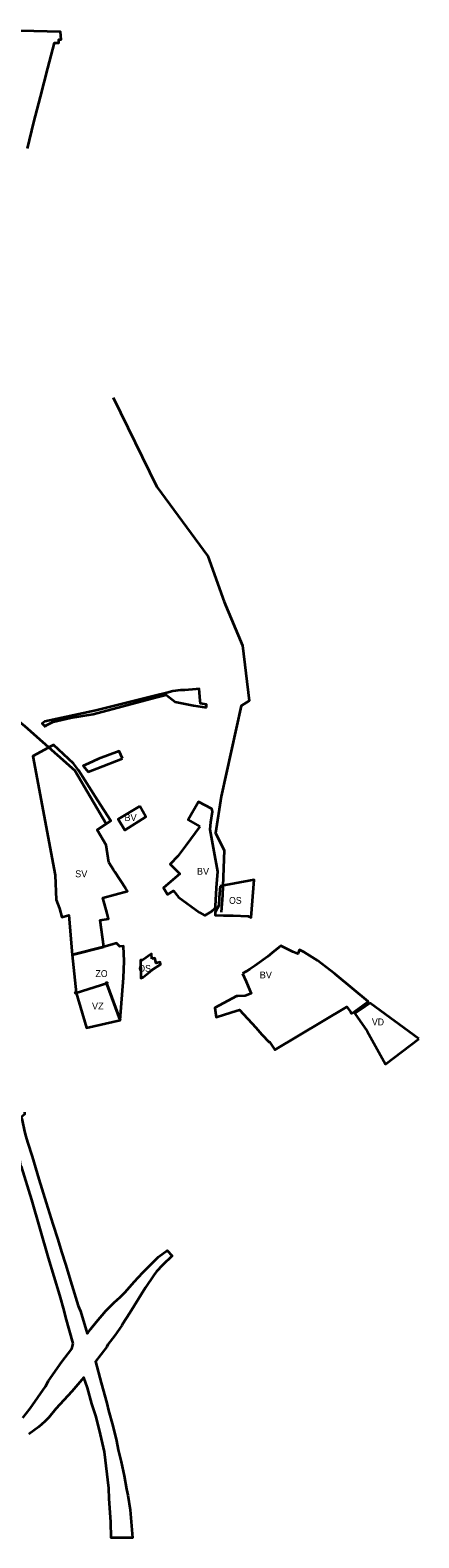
# Model space of a CAD drawing. Extents: x -650276 to -642489, y -1074311 to -1066658.
# Drawn here: x -645218 to -644537, y -1074038 to -1071399 of the extents above; entities that cross this region are included whole.
import ezdxf

# ---------------------------------------------------------------- set-up
doc = ezdxf.new("R2010")
doc.units = 0
doc.header["$LTSCALE"] = 4.8
doc.header["$PDMODE"] = 32
doc.header["$PDSIZE"] = 2.4
for name, color, linetype, lineweight in [('15', 7, 'Continuous', 35), ('18', 7, 'Continuous', 35), ('24', 7, 'Continuous', 35), ('3', 7, 'Continuous', 35), ('35', 7, 'Continuous', 35), ('36', 7, 'Continuous', 35), ('42', 7, 'Continuous', 35), ('54', 7, 'Continuous', 35), ('9', 7, 'Continuous', 35)]:
    doc.layers.add(name, color=color, linetype=linetype, lineweight=lineweight)
doc.layers.add('62', color=7, linetype='Continuous')

msp = doc.modelspace()

# ---------------------------------------------------------------- linework, layer by layer
at = {"layer": '15'}
for points in [[(-644926.81, -1072552.51), (-644946.57, -1072554.22), (-644954.57, -1072554.43), (-644967.97, -1072556.17), (-644978.56, -1072558.74), (-644999.72, -1072564.24), (-645102.73, -1072589.74), (-645192.06, -1072609.19), (-645197.044, -1072612.821), (-645190.71, -1072618.6)], [(-645147.13, -1072602.79), (-645107.58, -1072596.47), (-644997.92, -1072567.23), (-644979.55, -1072562.44), (-644963.97, -1072574.57)], [(-644919.75, -1072572.43), (-644921.84, -1072552.03), (-644926.81, -1072552.51)], [(-644963.97, -1072574.57), (-644931.48, -1072581.26), (-644909.02, -1072584.28)], [(-644909.02, -1072584.28), (-644908.59, -1072579.51), (-644919.23, -1072577.46), (-644919.75, -1072572.43)], [(-645190.71, -1072618.6), (-645190.59, -1072616.28), (-645179.6, -1072610.94), (-645177.56, -1072609.89), (-645147.13, -1072602.79)], [(-645056.08, -1072674.07), (-645062.131, -1072660.856), (-645098.016, -1072674.425), (-645115.56, -1072682.406), (-645124.933, -1072686.721), (-645116.11, -1072697.15)], [(-645116.11, -1072697.15), (-645100.9, -1072691.31), (-645056.08, -1072674.07)]]:
    msp.add_lwpolyline(points, dxfattribs=at)
at = {"layer": '18'}
msp.add_lwpolyline([(-645144.37, -1073017.64), (-645088.62, -1073003.45), (-645095.04, -1072957.07), (-645080.61, -1072954.43), (-645083.13, -1072944.94), (-645090.34, -1072917.86), (-645047.42, -1072906.05), (-645050.6, -1072901.03), (-645069.55, -1072872.12), (-645071.87, -1072868.45), (-645079.81, -1072855.89), (-645084.47, -1072825.67), (-645100.27, -1072798.46), (-645076.66, -1072783.06), (-645099.58, -1072746.945), (-645121.96, -1072711.68), (-645133.26, -1072694.17), (-645142.1, -1072682.57), (-645176.757, -1072649.968), (-645180.05, -1072651.77), (-645213.34, -1072669.98), (-645174.13, -1072877.93), (-645172.28, -1072921.42), (-645166.48, -1072936.5), (-645162.379, -1072951.55), (-645149.84, -1072948.13)], close=True, dxfattribs=at)
at = {"layer": '24'}
for points in [[(-645222.48, -1071606.08), (-645211.27, -1071560.01), (-645199.61, -1071515.68), (-645186.67, -1071465.55), (-645175.06, -1071420.93), (-645167.58, -1071421.19), (-645167.37, -1071415.2), (-645163.56, -1071415.3), (-645164.76, -1071401.79), (-645281.92, -1071398.82)], [(-645142.207, -1073697.878), (-645155.4, -1073652.618), (-645158.271, -1073639.962), (-645165.879, -1073613.368), (-645185.838, -1073547.75), (-645215.066, -1073446.251), (-645215.066, -1073446.251), (-645232.869, -1073388.079), (-645234.15, -1073388.3), (-645236.73, -1073372.92), (-645242.255, -1073352.652), (-645245.55, -1073343.196), (-645247.997, -1073332.992), (-645254.252, -1073315.648), (-645259.671, -1073298.157), (-645270.862, -1073292.263), (-645270.674, -1073289.436), (-645270.979, -1073285.096), (-645270.826, -1073282.937), (-645268.281, -1073278.357), (-645267.011, -1073277.282)], [(-645227.744, -1073292.736), (-645227.709, -1073297.105), (-645233.538, -1073301.748), (-645231.976, -1073307.175), (-645227.811, -1073326.92), (-645225.208, -1073335.374), (-645222.766, -1073345.378), (-645214.368, -1073370.824), (-645202.792, -1073410.042), (-645189.911, -1073451.528), (-645178.332, -1073489.109), (-645169.356, -1073515.725), (-645162.838, -1073537.623), (-645156.149, -1073559.097), (-645144.741, -1073595.63), (-645133.507, -1073631.745), (-645129.827, -1073641.333), (-645117.687, -1073680.357), (-645117.686, -1073680.357)], [(-645117.686, -1073680.357), (-645116.017, -1073678.548), (-645111.49, -1073672.015), (-645101.847, -1073660.215), (-645085.173, -1073640.634), (-645070.739, -1073625.929), (-645060.009, -1073616.53), (-645051.513, -1073608.124), (-645035.303, -1073590.199), (-645020.11, -1073573.585), (-644993.044, -1073546.324), (-644977.924, -1073535.072), (-644969.117, -1073544.254), (-644985.66, -1073560.69), (-644996.41, -1073571.97), (-645001.267, -1073578.582), (-645015.55, -1073599.96), (-645043.35, -1073644.04), (-645056.06, -1073664.2), (-645057, -1073666.46), (-645069.61, -1073683.97), (-645081.938, -1073699.551), (-645083.563, -1073703.795), (-645103.289, -1073729.161), (-645093.67, -1073766.618), (-645083.269, -1073802.165), (-645080.452, -1073815.426), (-645073.102, -1073842.105), (-645066.706, -1073868.355), (-645063.463, -1073884.343), (-645058.158, -1073905.265), (-645052.963, -1073929.814), (-645048.956, -1073952.909), (-645046.468, -1073963.613), (-645042.672, -1073989.007), (-645038.69, -1074038.132), (-645076.083, -1074038.132), (-645076.255, -1074009.906), (-645079.095, -1073970.117), (-645080.138, -1073950.909), (-645087.79, -1073887.702), (-645096.294, -1073849.905), (-645102.899, -1073824.258), (-645109.53, -1073803.725), (-645117.19, -1073775.726), (-645123.821, -1073757.192), (-645145.019, -1073782.052), (-645172.904, -1073812.299), (-645185.384, -1073827.415), (-645192.343, -1073834.369), (-645202.696, -1073843.79), (-645220.306, -1073856.451)], [(-645230.89, -1073828.274), (-645217.603, -1073811.984), (-645191.236, -1073772.952), (-645185.754, -1073763.32), (-645162.187, -1073729.808), (-645144.959, -1073707.044), (-645142.207, -1073697.878)]]:
    msp.add_lwpolyline(points, dxfattribs=at)
at = {"layer": '3'}
for points in [[(-645025.61, -1072757.17), (-645063.6, -1072780.26), (-645051.94, -1072799.21), (-645015.02, -1072776.01)], [(-644845.72, -1073050.14), (-644839.57, -1073064.5), (-644830.81, -1073084.98), (-644840.89, -1073089.3), (-644853.8, -1073089.99), (-644856.4, -1073090.13), (-644894.15, -1073110.3), (-644892.14, -1073126.36), (-644877.32, -1073121.83), (-644856.97, -1073115.6), (-644851, -1073113.77), (-644822.62, -1073144.71), (-644811.96, -1073156.75), (-644799.26, -1073170.13), (-644798.38, -1073169.56), (-644792.59, -1073178.73), (-644789.31, -1073183.93), (-644663.17, -1073108.27), (-644656.56, -1073117.4), (-644654.61, -1073120.1), (-644649.7, -1073116.65), (-644625.26, -1073099.51), (-644680.69, -1073053.67), (-644684.09, -1073050.8), (-644714.42, -1073027.62), (-644714.42, -1073027.62), (-644737.88, -1073012.62), (-644745.73, -1073008.64), (-644748.95, -1073015.64), (-644757.73, -1073012.05), (-644764.69, -1073008.87), (-644778.38, -1073001.84), (-644781.52, -1073004.39), (-644793.743, -1073014.293), (-644801.54, -1073020.61), (-644824.08, -1073036.56), (-644832.7, -1073042.34), (-644839.47, -1073046.89)]]:
    msp.add_lwpolyline(points, close=True, dxfattribs=at)
for points in [[(-644902.18, -1072797.88), (-644901.35, -1072785.36), (-644898.29, -1072766.55), (-644899.2, -1072762.14), (-644922.88, -1072749.97), (-644940.8, -1072781.48), (-644920.46, -1072792.92)], [(-644920.46, -1072792.92), (-644945.2, -1072826.3), (-644959.24, -1072844.92), (-644972.28, -1072859.02), (-644955.49, -1072875.78), (-644983.93, -1072900.24), (-644977.16, -1072912.11), (-644966.57, -1072905.23), (-644957.79, -1072916.73), (-644921.18, -1072943.17), (-644911.87, -1072948.76), (-644900.2, -1072941.67), (-644893.77, -1072935.88), (-644892.86, -1072932.6), (-644891.2, -1072900.09), (-644889.11, -1072871.66), (-644895.32, -1072836.6), (-644902.18, -1072797.88)]]:
    msp.add_lwpolyline(points, dxfattribs=at)
at = {"layer": '35'}
for points in [[(-644536.62, -1073164.33), (-644622.03, -1073101.88), (-644630.58, -1073107.78), (-644648.95, -1073120.47), (-644627.53, -1073151.26)], [(-644627.53, -1073151.26), (-644604.13, -1073193), (-644595.18, -1073208.98), (-644536.62, -1073164.33)]]:
    msp.add_lwpolyline(points, dxfattribs=at)
at = {"layer": '36'}
msp.add_lwpolyline([(-645137.5, -1073083.97), (-645119.34, -1073145.61), (-645060.1, -1073131.68), (-645082.6, -1073069.93), (-645083.681, -1073066.962)], dxfattribs=at)
for p in [(-645137.5, -1073083.97), (-645083.681, -1073066.962)]:
    msp.add_point(p, dxfattribs=at)
at = {"layer": '42'}
msp.add_lwpolyline([(-645054.12, -1073057.62), (-645052.94, -1073028.58), (-645054.44, -1073002.54), (-645060.95, -1073002.68), (-645066.66, -1072997.3), (-645074.333, -1072999.365), (-645088.62, -1073003.45), (-645144.37, -1073017.64), (-645137.5, -1073083.97), (-645083.681, -1073066.962), (-645082.6, -1073069.93), (-645060.1, -1073131.68)], close=True, dxfattribs=at)
at = {"layer": '54'}
for points in [[(-646336.784, -1071524.232), (-646218.737, -1071612.767), (-646164.374, -1071674.897), (-645904.456, -1071961.331), (-645718.199, -1072151.712), (-645526.944, -1072343.922), (-645538, -1072384), (-645459, -1072440), (-645389, -1072483), (-645335, -1072526), (-645287, -1072569), (-645227, -1072617), (-645139.573, -1072694.628), (-645084.365, -1072788.086)], [(-645072.161, -1072041.834), (-644995.618, -1072198.247), (-644906.317, -1072319.547), (-644877.614, -1072399.349), (-644845.721, -1072475.959), (-644833.873, -1072573.126), (-644848.261, -1072581.918), (-644882.834, -1072740.552), (-644893.098, -1072804.559), (-644878.097, -1072834.588), (-644880.803, -1072913.277), (-644882.834, -1072942.847)]]:
    msp.add_lwpolyline(points, dxfattribs=at)
at = {"layer": '9'}
for points in [[(-644884.712, -1072897.147), (-644886.418, -1072916.953), (-644887.44, -1072930.94), (-644893.37, -1072942.61), (-644893.59, -1072947.97), (-644878.86, -1072948.42), (-644861.93, -1072948.94), (-644835.99, -1072949.74), (-644830.25, -1072951.9), (-644825.25, -1072885.96)], [(-645004.82, -1073024.63), (-645005.31, -1073015.68), (-645021.1, -1073026.69), (-645024.71, -1073026.95), (-645023.6, -1073052.12), (-645023.88, -1073058.37), (-645019.57, -1073056.46), (-645007.99, -1073047.31), (-645003.78, -1073043.96), (-644989.34, -1073034.58), (-644990.25, -1073030.54), (-644997.09, -1073032.21), (-644999.23, -1073023.29)]]:
    msp.add_lwpolyline(points, close=True, dxfattribs=at)

# ---------------------------------------------------------------- texts
at = {"layer": '62'}
for s, p in [('BV', (-645052.614, -1072783.26)), ('SV', (-645139.013, -1072881.667)), ('BV', (-644925.614, -1072877.26)), ('BV', (-644815.563, -1073058.759)), ('VZ', (-645109.496, -1073113.102))]:
    msp.add_text(s, height=12, dxfattribs=at).set_placement(p)
at = {"layer": '62', "width": 0.95}
for s, p in [('OS', (-644869.265, -1072928.272)), ('OS', (-645028.265, -1073047.272)), ('ZO', (-645103.327, -1073056.309)), ('VD', (-644618.892, -1073140.939))]:
    msp.add_text(s, height=12, dxfattribs=at).set_placement(p)

doc.saveas('drawing.dxf')
